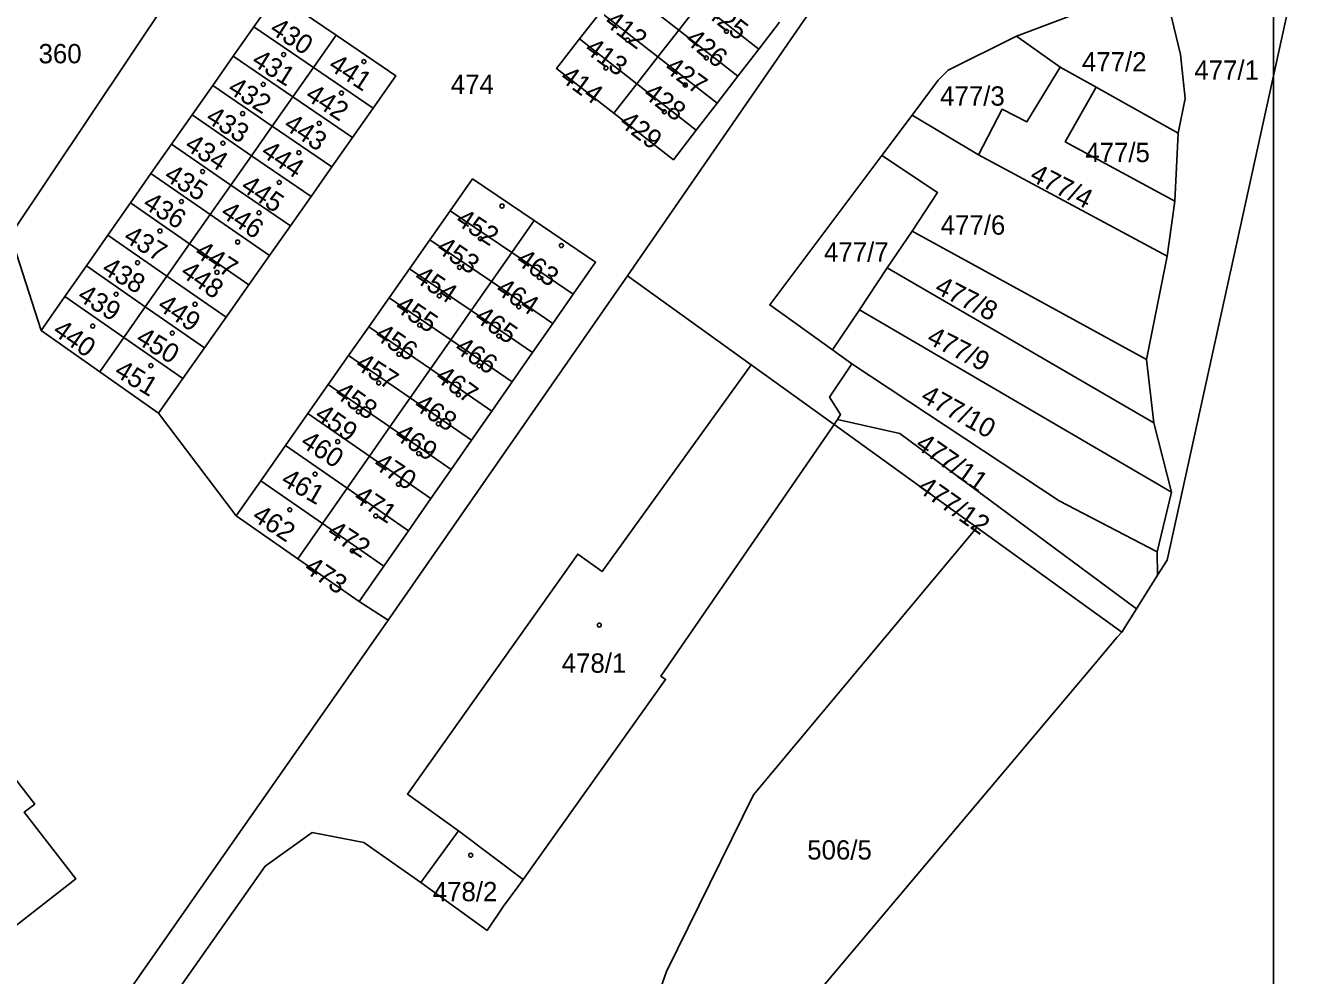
# Model space of a CAD drawing. Extents: x -558500 to -557517, y -1073973 to -1073051.
# Drawn here: x -557909.9 to -557797.9, y -1073426.7 to -1073343.1 of the extents above; entities that cross this region are included whole.
import ezdxf

# ---------------------------------------------------------------- set-up
doc = ezdxf.new("R2010")
doc.units = 0
for name, color, linetype in [('Default', 7, 'Continuous'), ('Hranice parcel', 7, 'Continuous'), ('Parcelní čísla', 7, 'Continuous'), ('Značky budov', 7, 'Continuous')]:
    doc.layers.add(name, color=color, linetype=linetype)

msp = doc.modelspace()

# ---------------------------------------------------------------- linework, layer by layer
at = {"layer": 'Default'}
msp.add_lwpolyline([(-557909.21, -1073700), (-558500, -1073700), (-558500, -1073200), (-557800, -1073200), (-557800, -1073567.6)], dxfattribs=at)
at = {"layer": 'Hranice parcel'}
for p, q in [((-557911.2, -1073361.51), (-557892.99, -1073334.25)), ((-557809.37, -1073390.13), (-557797.89, -1073337.76)), ((-557857.41, -1073339.54), (-557852.37, -1073343.47)), ((-557809.74, -1073339.14), (-557822.65, -1073343.99)), ((-557859.26, -1073341.9), (-557861.1, -1073344.25)), ((-557859.26, -1073341.9), (-557854.22, -1073345.83)), ((-557852.37, -1073343.47), (-557850.52, -1073341.11)), ((-557850.52, -1073341.11), (-557845.33, -1073345.15)), ((-557845.33, -1073345.15), (-557843.49, -1073342.78)), ((-557889.79, -1073343.18), (-557891.6, -1073345.76)), ((-557889.79, -1073343.18), (-557884.54, -1073346.76)), ((-557884.54, -1073346.76), (-557882.54, -1073343.92)), ((-557861.1, -1073344.25), (-557856.06, -1073348.19)), ((-557854.22, -1073345.83), (-557852.37, -1073343.47)), ((-557852.37, -1073343.47), (-557847.16, -1073347.52)), ((-557822.65, -1073343.99), (-557818.8, -1073346.73)), ((-557847.16, -1073347.52), (-557845.33, -1073345.15)), ((-557891.6, -1073345.76), (-557893.41, -1073348.34)), ((-557891.6, -1073345.76), (-557886.35, -1073349.35)), ((-557856.06, -1073348.19), (-557854.22, -1073345.83)), ((-557854.22, -1073345.83), (-557849, -1073349.9)), ((-557886.35, -1073349.35), (-557884.54, -1073346.76)), ((-557884.54, -1073346.76), (-557879.29, -1073350.34)), ((-557849, -1073349.9), (-557847.16, -1073347.52)), ((-557818.8, -1073346.73), (-557815.63, -1073348.5)), ((-557893.41, -1073348.34), (-557895.22, -1073350.93)), ((-557893.41, -1073348.34), (-557888.17, -1073351.94)), ((-557858.09, -1073350.78), (-557856.06, -1073348.19)), ((-557856.06, -1073348.19), (-557850.83, -1073352.27)), ((-557815.63, -1073348.5), (-557808.41, -1073352.55)), ((-557888.17, -1073351.94), (-557886.35, -1073349.35)), ((-557886.35, -1073349.35), (-557881.11, -1073352.93)), ((-557895.22, -1073350.93), (-557897.03, -1073353.51)), ((-557895.22, -1073350.93), (-557889.99, -1073354.53)), ((-557881.11, -1073352.93), (-557879.29, -1073350.34)), ((-557850.83, -1073352.27), (-557849, -1073349.9)), ((-557831.83, -1073350.97), (-557834.5, -1073354.52)), ((-557831.83, -1073350.97), (-557825.97, -1073354.44)), ((-557889.99, -1073354.53), (-557888.17, -1073351.94)), ((-557888.17, -1073351.94), (-557882.93, -1073355.52)), ((-557882.93, -1073355.52), (-557881.11, -1073352.93)), ((-557808.41, -1073352.55), (-557808.71, -1073358.52)), ((-557897.03, -1073353.51), (-557898.84, -1073356.1)), ((-557897.03, -1073353.51), (-557891.81, -1073357.12)), ((-557891.81, -1073357.12), (-557889.99, -1073354.53)), ((-557889.99, -1073354.53), (-557884.75, -1073358.12)), ((-557825.97, -1073354.44), (-557809.38, -1073363.37)), ((-557898.84, -1073356.1), (-557900.65, -1073358.68)), ((-557898.84, -1073356.1), (-557893.62, -1073359.71)), ((-557884.75, -1073358.12), (-557882.93, -1073355.52)), ((-557893.62, -1073359.71), (-557891.81, -1073357.12)), ((-557891.81, -1073357.12), (-557886.57, -1073360.71)), ((-557900.65, -1073358.68), (-557902.64, -1073361.52)), ((-557900.65, -1073358.68), (-557895.44, -1073362.3)), ((-557886.57, -1073360.71), (-557884.75, -1073358.12)), ((-557808.71, -1073358.52), (-557809.38, -1073363.37)), ((-557895.44, -1073362.3), (-557893.62, -1073359.71)), ((-557893.62, -1073359.71), (-557888.4, -1073363.3)), ((-557872.5, -1073359.38), (-557874.29, -1073361.93)), ((-557872.5, -1073359.38), (-557867.08, -1073363.05)), ((-557888.4, -1073363.3), (-557886.57, -1073360.71)), ((-557867.08, -1073363.05), (-557865.11, -1073360.23)), ((-557911.2, -1073361.51), (-557908.52, -1073369.92)), ((-557902.64, -1073361.52), (-557904.53, -1073364.22)), ((-557902.64, -1073361.52), (-557897.44, -1073365.14)), ((-557874.29, -1073361.93), (-557876.07, -1073364.48)), ((-557874.29, -1073361.93), (-557868.87, -1073365.61)), ((-557834.02, -1073364.39), (-557831.83, -1073361.18)), ((-557831.83, -1073361.18), (-557811.19, -1073372.48)), ((-557897.44, -1073365.14), (-557895.44, -1073362.3)), ((-557895.44, -1073362.3), (-557890.22, -1073365.89)), ((-557868.87, -1073365.61), (-557867.08, -1073363.05)), ((-557867.08, -1073363.05), (-557861.66, -1073366.72)), ((-557904.53, -1073364.22), (-557906.42, -1073366.92)), ((-557904.53, -1073364.22), (-557899.34, -1073367.84)), ((-557890.22, -1073365.89), (-557888.4, -1073363.3)), ((-557836.47, -1073368.11), (-557834.02, -1073364.39)), ((-557834.02, -1073364.39), (-557810.53, -1073378.05)), ((-557809.38, -1073363.37), (-557811.19, -1073372.48)), ((-557899.34, -1073367.84), (-557897.44, -1073365.14)), ((-557897.44, -1073365.14), (-557892.22, -1073368.74)), ((-557877.97, -1073395.43), (-557856.89, -1073365.11)), ((-557876.07, -1073364.48), (-557877.86, -1073367.03)), ((-557876.07, -1073364.48), (-557870.66, -1073368.17)), ((-557856.89, -1073365.11), (-557845.99, -1073372.93)), ((-557892.22, -1073368.74), (-557890.22, -1073365.89)), ((-557870.66, -1073368.17), (-557868.87, -1073365.61)), ((-557868.87, -1073365.61), (-557863.45, -1073369.29)), ((-557906.42, -1073366.92), (-557908.52, -1073369.92)), ((-557906.42, -1073366.92), (-557901.24, -1073370.54)), ((-557877.86, -1073367.03), (-557879.65, -1073369.58)), ((-557877.86, -1073367.03), (-557872.45, -1073370.73)), ((-557863.45, -1073369.29), (-557861.66, -1073366.72)), ((-557901.24, -1073370.54), (-557899.34, -1073367.84)), ((-557899.34, -1073367.84), (-557894.12, -1073371.44)), ((-557894.12, -1073371.44), (-557892.22, -1073368.74)), ((-557872.45, -1073370.73), (-557870.66, -1073368.17)), ((-557870.66, -1073368.17), (-557865.24, -1073371.86)), ((-557838.83, -1073371.62), (-557836.47, -1073368.11)), ((-557836.47, -1073368.11), (-557808.98, -1073384.15)), ((-557908.52, -1073369.92), (-557903.35, -1073373.55)), ((-557879.65, -1073369.58), (-557881.44, -1073372.13)), ((-557879.65, -1073369.58), (-557874.24, -1073373.29)), ((-557865.24, -1073371.86), (-557863.45, -1073369.29)), ((-557903.35, -1073373.55), (-557901.24, -1073370.54)), ((-557901.24, -1073370.54), (-557896.03, -1073374.15)), ((-557874.24, -1073373.29), (-557872.45, -1073370.73)), ((-557872.45, -1073370.73), (-557867.03, -1073374.43)), ((-557896.03, -1073374.15), (-557894.12, -1073371.44)), ((-557881.44, -1073372.13), (-557883.23, -1073374.68)), ((-557881.44, -1073372.13), (-557876.02, -1073375.85)), ((-557867.03, -1073374.43), (-557865.24, -1073371.86)), ((-557837.14, -1073372.84), (-557838.83, -1073371.62)), ((-557876.02, -1073375.85), (-557874.24, -1073373.29)), ((-557874.24, -1073373.29), (-557868.82, -1073377.01)), ((-557838.68, -1073378.19), (-557845.99, -1073372.93)), ((-557837.14, -1073372.84), (-557818.89, -1073384.91)), ((-557811.19, -1073372.48), (-557810.53, -1073378.05)), ((-557903.35, -1073373.55), (-557898.17, -1073377.19)), ((-557898.17, -1073377.19), (-557896.03, -1073374.15)), ((-557868.82, -1073377.01), (-557867.03, -1073374.43)), ((-557883.23, -1073374.68), (-557885.02, -1073377.23)), ((-557883.23, -1073374.68), (-557877.81, -1073378.41)), ((-557877.81, -1073378.41), (-557876.02, -1073375.85)), ((-557876.02, -1073375.85), (-557870.61, -1073379.58)), ((-557898.17, -1073377.19), (-557891.33, -1073386.24)), ((-557885.02, -1073377.23), (-557886.99, -1073380.04)), ((-557885.02, -1073377.23), (-557879.6, -1073380.98)), ((-557870.61, -1073379.58), (-557868.82, -1073377.01)), ((-557838.68, -1073378.19), (-557838.4, -1073377.75)), ((-557879.6, -1073380.98), (-557877.81, -1073378.41)), ((-557877.81, -1073378.41), (-557872.4, -1073382.15)), ((-557838.68, -1073378.19), (-557826.12, -1073387.26)), ((-557810.53, -1073378.05), (-557808.98, -1073384.15)), ((-557886.99, -1073380.04), (-557889.16, -1073383.14)), ((-557886.99, -1073380.04), (-557881.57, -1073383.79)), ((-557872.4, -1073382.15), (-557870.61, -1073379.58)), ((-557881.57, -1073383.79), (-557879.6, -1073380.98)), ((-557879.6, -1073380.98), (-557874.19, -1073384.72)), ((-557874.19, -1073384.72), (-557872.4, -1073382.15)), ((-557889.16, -1073383.14), (-557891.33, -1073386.24)), ((-557889.16, -1073383.14), (-557883.75, -1073386.9)), ((-557883.75, -1073386.9), (-557881.57, -1073383.79)), ((-557881.57, -1073383.79), (-557876.16, -1073387.55)), ((-557808.98, -1073384.15), (-557810.24, -1073389.4)), ((-557876.16, -1073387.55), (-557874.19, -1073384.72)), ((-557818.89, -1073384.91), (-557810.24, -1073389.4)), ((-557891.33, -1073386.24), (-557885.92, -1073390.01)), ((-557885.92, -1073390.01), (-557883.75, -1073386.9)), ((-557883.75, -1073386.9), (-557878.33, -1073390.67)), ((-557878.33, -1073390.67), (-557876.16, -1073387.55)), ((-557826.12, -1073387.26), (-557813.37, -1073396.47)), ((-557885.92, -1073390.01), (-557880.51, -1073393.79)), ((-557810.24, -1073389.4), (-557810.21, -1073391.46)), ((-557810.21, -1073391.46), (-557809.37, -1073390.13)), ((-557880.51, -1073393.79), (-557878.33, -1073390.67)), ((-557812.08, -1073394.43), (-557810.21, -1073391.46)), ((-557880.51, -1073393.79), (-557877.97, -1073395.43)), ((-557813.37, -1073396.47), (-557812.08, -1073394.43)), ((-557813.37, -1073396.47), (-557813.79, -1073396.96)), ((-557813.79, -1073396.96), (-557815.73, -1073399.27)), ((-557834.15, -1073421.11), (-557815.73, -1073399.27)), ((-557871.76, -1073413.96), (-557875.08, -1073418.52)), ((-557871.76, -1073413.96), (-557866.06, -1073418.25))]:
    msp.add_line(p, q, dxfattribs=at)
for points in [[(-558022.09, -1073311.21), (-558020.08, -1073313.87), (-558000.41, -1073328.2), (-557993.92, -1073334.5), (-557986.04, -1073343.93), (-557967.1, -1073369.2), (-557918.24, -1073434.51), (-557914.64, -1073436.24), (-557909.55, -1073436.22), (-557905.05, -1073434.1), (-557902.57, -1073430.65), (-557891.22, -1073414.37), (-557877.97, -1073395.43)], [(-557856.89, -1073365.11), (-557824.85, -1073318.68), (-557819.71, -1073312.13)], [(-557809.74, -1073339.14), (-557808.21, -1073345.61), (-557807.79, -1073349.5), (-557808.41, -1073352.55)], [(-557882.54, -1073343.92), (-557887.8, -1073340.34), (-557889.79, -1073343.18)], [(-557879.29, -1073350.34), (-557877.28, -1073347.5), (-557882.54, -1073343.92)], [(-557861.1, -1073344.25), (-557863.13, -1073346.85), (-557858.09, -1073350.78)], [(-557822.65, -1073343.99), (-557828.66, -1073347), (-557829.52, -1073347.89), (-557831.83, -1073350.97)], [(-557825.97, -1073354.44), (-557823.9, -1073350.44), (-557821.72, -1073351.54), (-557818.8, -1073346.73)], [(-557808.71, -1073358.52), (-557818.34, -1073353.3), (-557815.63, -1073348.5)], [(-557858.09, -1073350.78), (-557852.85, -1073354.88), (-557850.83, -1073352.27)], [(-557838.83, -1073371.62), (-557844.36, -1073367.66), (-557834.5, -1073354.52)], [(-557834.5, -1073354.52), (-557829.59, -1073357.77), (-557831.83, -1073361.18)], [(-557865.11, -1073360.23), (-557870.53, -1073356.57), (-557872.5, -1073359.38)], [(-557861.66, -1073366.72), (-557859.69, -1073363.89), (-557865.11, -1073360.23)], [(-557845.99, -1073372.93), (-557859.12, -1073391.15), (-557861.27, -1073389.6), (-557876.27, -1073410.74), (-557871.76, -1073413.96)], [(-557838.4, -1073377.75), (-557838.12, -1073377.3), (-557839.1, -1073375.8), (-557837.14, -1073372.84)], [(-557838.4, -1073377.75), (-557832.9, -1073378.99), (-557812.08, -1073394.43)], [(-557866.06, -1073418.25), (-557853.54, -1073400.64), (-557853.96, -1073400.34), (-557838.68, -1073378.19)], [(-557861.36, -1073465.07), (-557859.38, -1073443.12), (-557853.44, -1073426.35), (-557845.8, -1073410.81), (-557826.12, -1073387.26)], [(-557930.26, -1073400.48), (-557932.35, -1073402.1), (-557927.81, -1073407.96), (-557928.68, -1073408.63), (-557926.46, -1073411.51), (-557925.59, -1073410.83), (-557921.19, -1073416.52), (-557922.06, -1073417.2), (-557919.87, -1073420.02), (-557919, -1073419.35), (-557914.46, -1073425.22), (-557905.47, -1073418.2), (-557910.01, -1073412.34), (-557909.08, -1073411.62), (-557911.27, -1073408.79), (-557912.2, -1073409.51), (-557916.62, -1073403.8), (-557915.7, -1073403.08), (-557917.89, -1073400.24), (-557918.82, -1073400.96), (-557923.37, -1073395.09)], [(-557875.08, -1073418.52), (-557880.11, -1073415), (-557884.66, -1073414.11), (-557888.78, -1073417.07), (-557919.08, -1073460.09), (-557919.51, -1073465.45), (-557958.15, -1073519.56), (-557960.76, -1073525.37), (-557961.25, -1073531.9), (-557959.85, -1073543.64), (-557958.52, -1073546.41), (-557955.67, -1073549.33), (-557941.9, -1073559.58)], [(-557875.08, -1073418.52), (-557869.25, -1073422.74), (-557867.79, -1073420.61), (-557866.54, -1073418.89), (-557866.06, -1073418.25)], [(-557834.15, -1073421.11), (-557844.86, -1073433.81), (-557856.07, -1073452.41), (-557861.36, -1073465.07)]]:
    msp.add_lwpolyline(points, dxfattribs=at)
at = {"layer": 'Značky budov'}
for centre in [(-557856.88, -1073344.34), (-557848.17, -1073343.57), (-557887.16, -1073345.62), (-557880.1, -1073346.24), (-557849.95, -1073345.91), (-557858.79, -1073346.8), (-557888.96, -1073348.25), (-557851.8, -1073348.3), (-557882.07, -1073349.01), (-557890.77, -1073350.82), (-557853.64, -1073350.66), (-557884.03, -1073351.68), (-557892.51, -1073353.43), (-557885.82, -1073354.26), (-557894.3, -1073355.92), (-557887.55, -1073356.88), (-557896.16, -1073358.56), (-557867.93, -1073358.96), (-557889.33, -1073359.55), (-557898.05, -1073361.16), (-557891.21, -1073362.13), (-557869.83, -1073361.84), (-557862.71, -1073362.44), (-557900.02, -1073363.95), (-557871.67, -1073364.36), (-557893.03, -1073364.8), (-557864.65, -1073365.25), (-557901.91, -1073366.72), (-557894.96, -1073367.61), (-557873.46, -1073366.87), (-557866.46, -1073367.83), (-557903.97, -1073369.53), (-557896.97, -1073370.15), (-557875.18, -1073369.44), (-557868.22, -1073370.41), (-557877.01, -1073372.01), (-557898.85, -1073373.01), (-557869.95, -1073373.03), (-557878.79, -1073374.53), (-557871.78, -1073375.57), (-557880.58, -1073377.07), (-557873.54, -1073378.14), (-557882.4, -1073379.7), (-557875.27, -1073380.75), (-557884.39, -1073382.56), (-557877.05, -1073383.46), (-557886.62, -1073385.7), (-557879.05, -1073386.25), (-557881.11, -1073389.32), (-557859.37, -1073395.86), (-557870.69, -1073416.12)]:
    msp.add_circle(centre, 0.175, dxfattribs=at)

# ---------------------------------------------------------------- texts
at = {"layer": 'Parcelní čísla'}
for s, rotation, p in [('425', 322, (-557850.11, -1073342.12)), ('430', 327, (-557888.49, -1073343.66)), ('412', 323, (-557859.02, -1073342.96)), ('426', 321, (-557851.91, -1073344.49)), ('413', 324, (-557860.76, -1073345.36)), ('431', 328, (-557890.08, -1073346.47)), ('441', 327, (-557883.32, -1073346.85)), ('427', 324, (-557853.74, -1073347.03)), ('414', 324, (-557862.92, -1073347.85)), ('432', 328, (-557892.19, -1073348.9)), ('442', 327, (-557885.36, -1073349.49)), ('428', 323, (-557855.61, -1073349.29)), ('433', 328, (-557894.13, -1073351.48)), ('429', 323, (-557857.71, -1073351.8)), ('443', 326, (-557887.26, -1073352.08)), ('434', 327, (-557895.98, -1073353.89)), ('444', 326, (-557889.27, -1073354.46)), ('435', 328, (-557897.79, -1073356.58)), ('445', 326, (-557891.04, -1073357.5)), ('477/4', 333, (-557821.57, -1073356.66)), ('436', 328, (-557899.67, -1073359.04)), ('446', 326, (-557892.82, -1073359.8)), ('452', 327, (-557872.13, -1073360.48)), ('437', 329, (-557901.36, -1073362)), ('453', 326, (-557873.82, -1073362.91)), ('447', 327, (-557895.11, -1073363.31)), ('463', 325, (-557866.82, -1073363.96)), ('438', 329, (-557903.28, -1073364.79)), ('448', 325, (-557896.35, -1073365.03)), ('454', 326, (-557875.78, -1073365.49)), ('477/8', 333, (-557829.94, -1073366.55)), ('439', 328, (-557905.42, -1073367.16)), ('464', 327, (-557868.6, -1073366.58)), ('449', 326, (-557898.38, -1073367.98)), ('455', 326, (-557877.48, -1073368.08)), ('465', 325, (-557870.46, -1073369)), ('440', 325, (-557907.6, -1073370.19)), ('450', 329, (-557900.28, -1073370.96)), ('456', 326, (-557879.26, -1073370.56)), ('477/9', 333, (-557830.64, -1073370.98)), ('466', 326, (-557872.22, -1073371.73)), ('457', 327, (-557880.97, -1073373.18)), ('451', 329, (-557902.18, -1073373.84)), ('467', 324, (-557873.92, -1073374.23)), ('458', 325, (-557882.8, -1073375.67)), ('477/10', 331, (-557831.18, -1073376.1)), ('459', 325, (-557884.54, -1073377.63)), ('468', 326, (-557875.81, -1073376.75)), ('469', 326, (-557877.52, -1073379.37)), ('460', 327, (-557885.79, -1073380.03)), ('477/11', 325, (-557831.64, -1073380.2)), ('470', 326, (-557879.37, -1073381.93)), ('461', 330, (-557887.5, -1073383.42)), ('477/12', 325, (-557831.47, -1073384)), ('471', 326, (-557881.11, -1073384.86)), ('462', 327, (-557890.05, -1073386.55)), ('472', 327, (-557883.44, -1073387.95)), ('473', 326, (-557885.47, -1073391.09))]:
    msp.add_text(s, height=1.7, rotation=rotation, dxfattribs=at).set_placement(p)
for s, p in [('360', (-557908.74, -1073346.39)), ('477/2', (-557816.88, -1073347.11)), ('477/1', (-557806.98, -1073347.84)), ('474', (-557872.44, -1073349.09)), ('477/3', (-557829.36, -1073350.12)), ('477/5', (-557816.58, -1073355.09)), ('477/6', (-557829.31, -1073361.48)), ('477/7', (-557839.58, -1073363.85)), ('478/1', (-557862.68, -1073400.05)), ('506/5', (-557841.06, -1073416.5)), ('478/2', (-557874.03, -1073420.17))]:
    msp.add_text(s, height=1.7, dxfattribs=at).set_placement(p)

doc.saveas('drawing.dxf')
